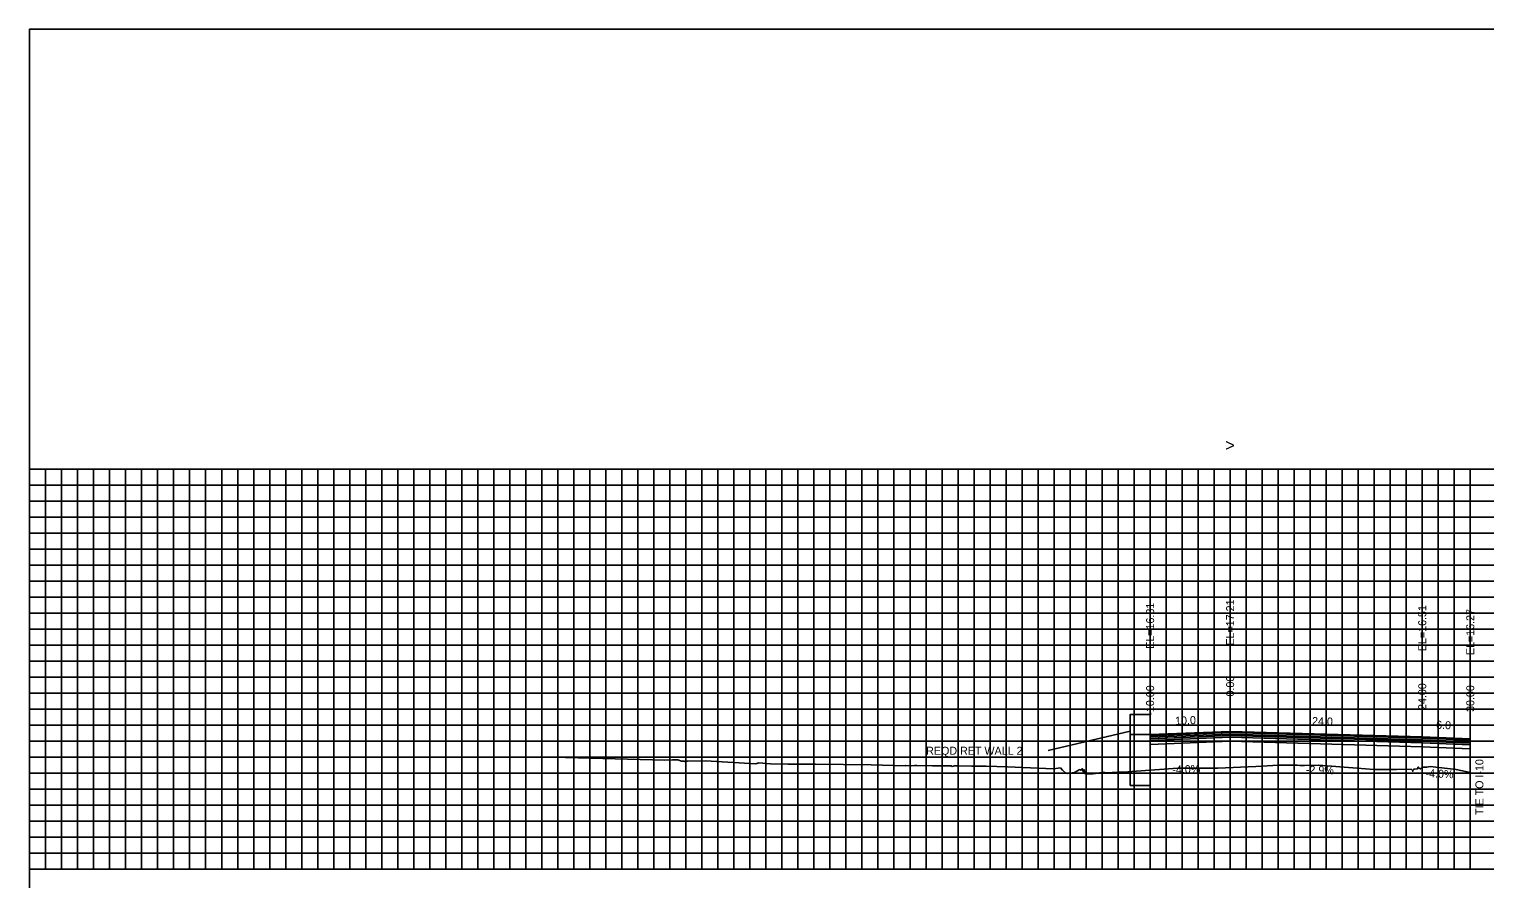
# Model space of a CAD drawing. Extents: x 1797518 to 1804843, y 248068 to 251132.
# Drawn here: x 1803840.9 to 1804022.8, y 250163.2 to 250269.4 of the extents above; entities that cross this region are included whole.
import ezdxf

# ---------------------------------------------------------------- set-up
doc = ezdxf.new("R2010")
doc.units = 0
for name, color, linetype in [('3', 7, 'Continuous'), ('4', 7, 'Continuous'), ('60', 7, 'Continuous'), ('BASE', 7, 'Continuous'), ('CL-CNST', 7, 'Continuous'), ('Level 62', 7, 'Continuous'), ('LOWER BINDER', 7, 'Continuous'), ('M-ROADS', 7, 'Continuous'), ('UPPER BINDER', 7, 'Continuous'), ('WEARING', 7, 'Continuous')]:
    doc.layers.add(name, color=color, linetype=linetype)

msp = doc.modelspace()

# ---------------------------------------------------------------- linework, layer by layer
for p, q in [((1803981, 250181.25), (1803981, 250183.25)), ((1803991, 250181.65), (1803991, 250183.65)), ((1804015, 250180.95), (1804015, 250182.95)), ((1804021, 250180.71), (1804021, 250182.71))]:
    msp.add_line(p, q)
msp.add_lwpolyline([(1803841, 250079.43), (1804141, 250079.43), (1804141, 250269.43), (1803841, 250269.43)], close=True)
at = {"layer": '3'}
for p, q in [((1803968.28, 250179.28), (1803978.5, 250181.68)), ((1804021, 250181.46), (1804021, 250171.43))]:
    msp.add_line(p, q, dxfattribs=at)
at = {"layer": '60'}
for p, q in [((1803840.94, 250214.43), (1803841, 250214.43)), ((1803841, 250164.43), (1803841, 250214.43)), ((1803840.94, 250204.43), (1803841, 250204.43)), ((1803840.94, 250194.43), (1803841, 250194.43)), ((1803840.94, 250184.43), (1803841, 250184.43)), ((1803840.94, 250174.43), (1803841, 250174.43)), ((1803840.94, 250164.43), (1803841, 250164.43)), ((1803841, 250164.43), (1804141, 250164.43)), ((1803841, 250164.37), (1803841, 250164.43)), ((1803851, 250164.37), (1803851, 250164.43)), ((1803861, 250164.37), (1803861, 250164.43)), ((1803871, 250164.37), (1803871, 250164.43)), ((1803881, 250164.37), (1803881, 250164.43)), ((1803891, 250164.37), (1803891, 250164.43)), ((1803901, 250164.37), (1803901, 250164.43)), ((1803911, 250164.37), (1803911, 250164.43)), ((1803921, 250164.37), (1803921, 250164.43)), ((1803931, 250164.37), (1803931, 250164.43)), ((1803941, 250164.37), (1803941, 250164.43)), ((1803951, 250164.37), (1803951, 250164.43)), ((1803961, 250164.37), (1803961, 250164.43)), ((1803971, 250164.37), (1803971, 250164.43)), ((1803981, 250164.37), (1803981, 250164.43)), ((1803991, 250164.37), (1803991, 250164.43)), ((1804001, 250164.37), (1804001, 250164.43)), ((1804011, 250164.37), (1804011, 250164.43)), ((1804021, 250164.37), (1804021, 250164.43))]:
    msp.add_line(p, q, dxfattribs=at)
at = {"layer": 'BASE'}
msp.add_lwpolyline([(1803981, 250180.53), (1803991, 250180.93), (1804015, 250180.23), (1804021, 250179.98), (1804021, 250179.48), (1804015, 250179.73), (1803991, 250180.43), (1803981, 250180.03)], close=True, dxfattribs=at)
at = {"layer": 'CL-CNST'}
for points in [[(1803981, 250181.25), (1803978.5, 250181.25), (1803978.5, 250183.75), (1803981, 250183.75)], [(1803978.5, 250174.87), (1803981, 250174.87), (1803981, 250181.25), (1803978.5, 250181.25)]]:
    msp.add_lwpolyline(points, close=True, dxfattribs=at)
msp.add_lwpolyline([(1803981, 250181.25), (1803991, 250181.65), (1804015, 250180.95), (1804021, 250180.71)], dxfattribs=at)
at = {"layer": 'Level 62'}
for p, q in [((1803841, 250214.43), (1804141, 250214.43)), ((1803841, 250164.43), (1803841, 250214.43)), ((1803843, 250164.43), (1803843, 250214.43)), ((1803845, 250164.43), (1803845, 250214.43)), ((1803847, 250164.43), (1803847, 250214.43)), ((1803849, 250164.43), (1803849, 250214.43)), ((1803851, 250164.43), (1803851, 250214.43)), ((1803853, 250164.43), (1803853, 250214.43)), ((1803855, 250164.43), (1803855, 250214.43)), ((1803857, 250164.43), (1803857, 250214.43)), ((1803859, 250164.43), (1803859, 250214.43)), ((1803861, 250164.43), (1803861, 250214.43)), ((1803863, 250164.43), (1803863, 250214.43)), ((1803865, 250164.43), (1803865, 250214.43)), ((1803867, 250164.43), (1803867, 250214.43)), ((1803869, 250164.43), (1803869, 250214.43)), ((1803871, 250164.43), (1803871, 250214.43)), ((1803873, 250164.43), (1803873, 250214.43)), ((1803875, 250164.43), (1803875, 250214.43)), ((1803877, 250164.43), (1803877, 250214.43)), ((1803879, 250164.43), (1803879, 250214.43)), ((1803881, 250164.43), (1803881, 250214.43)), ((1803883, 250164.43), (1803883, 250214.43)), ((1803885, 250164.43), (1803885, 250214.43)), ((1803887, 250164.43), (1803887, 250214.43)), ((1803889, 250164.43), (1803889, 250214.43)), ((1803891, 250164.43), (1803891, 250214.43)), ((1803893, 250164.43), (1803893, 250214.43)), ((1803895, 250164.43), (1803895, 250214.43)), ((1803897, 250164.43), (1803897, 250214.43)), ((1803899, 250164.43), (1803899, 250214.43)), ((1803901, 250164.43), (1803901, 250214.43)), ((1803903, 250164.43), (1803903, 250214.43)), ((1803905, 250164.43), (1803905, 250214.43)), ((1803907, 250164.43), (1803907, 250214.43)), ((1803909, 250164.43), (1803909, 250214.43)), ((1803911, 250164.43), (1803911, 250214.43)), ((1803913, 250164.43), (1803913, 250214.43)), ((1803915, 250164.43), (1803915, 250214.43)), ((1803917, 250164.43), (1803917, 250214.43)), ((1803919, 250164.43), (1803919, 250214.43)), ((1803921, 250164.43), (1803921, 250214.43)), ((1803923, 250164.43), (1803923, 250214.43)), ((1803925, 250164.43), (1803925, 250214.43)), ((1803927, 250164.43), (1803927, 250214.43)), ((1803929, 250164.43), (1803929, 250214.43)), ((1803931, 250164.43), (1803931, 250214.43)), ((1803933, 250164.43), (1803933, 250214.43)), ((1803935, 250164.43), (1803935, 250214.43)), ((1803937, 250164.43), (1803937, 250214.43)), ((1803939, 250164.43), (1803939, 250214.43)), ((1803941, 250164.43), (1803941, 250214.43)), ((1803943, 250164.43), (1803943, 250214.43)), ((1803945, 250164.43), (1803945, 250214.43)), ((1803947, 250164.43), (1803947, 250214.43)), ((1803949, 250164.43), (1803949, 250214.43)), ((1803951, 250164.43), (1803951, 250214.43)), ((1803953, 250164.43), (1803953, 250214.43)), ((1803955, 250164.43), (1803955, 250214.43)), ((1803957, 250164.43), (1803957, 250214.43)), ((1803959, 250164.43), (1803959, 250214.43)), ((1803961, 250164.43), (1803961, 250214.43)), ((1803963, 250164.43), (1803963, 250214.43)), ((1803965, 250164.43), (1803965, 250214.43)), ((1803967, 250164.43), (1803967, 250214.43)), ((1803969, 250164.43), (1803969, 250214.43)), ((1803971, 250164.43), (1803971, 250214.43)), ((1803973, 250164.43), (1803973, 250214.43)), ((1803975, 250164.43), (1803975, 250214.43)), ((1803977, 250164.43), (1803977, 250214.43)), ((1803979, 250164.43), (1803979, 250214.43)), ((1803981, 250164.43), (1803981, 250214.43)), ((1803983, 250164.43), (1803983, 250214.43)), ((1803985, 250164.43), (1803985, 250214.43)), ((1803987, 250164.43), (1803987, 250214.43)), ((1803989, 250164.43), (1803989, 250214.43)), ((1803991, 250164.43), (1803991, 250214.43)), ((1803993, 250164.43), (1803993, 250214.43)), ((1803995, 250164.43), (1803995, 250214.43)), ((1803997, 250164.43), (1803997, 250214.43)), ((1803999, 250164.43), (1803999, 250214.43)), ((1804001, 250164.43), (1804001, 250214.43)), ((1804003, 250164.43), (1804003, 250214.43)), ((1804005, 250164.43), (1804005, 250214.43)), ((1804007, 250164.43), (1804007, 250214.43)), ((1804009, 250164.43), (1804009, 250214.43)), ((1804011, 250164.43), (1804011, 250214.43)), ((1804013, 250164.43), (1804013, 250214.43)), ((1804015, 250164.43), (1804015, 250214.43)), ((1804017, 250164.43), (1804017, 250214.43)), ((1804019, 250164.43), (1804019, 250214.43)), ((1804021, 250164.43), (1804021, 250214.43)), ((1803841, 250212.43), (1804141, 250212.43)), ((1803841, 250210.43), (1804141, 250210.43)), ((1803841, 250208.43), (1804141, 250208.43)), ((1803841, 250206.43), (1804141, 250206.43)), ((1803841, 250204.43), (1804141, 250204.43)), ((1803841, 250202.43), (1804141, 250202.43)), ((1803841, 250200.43), (1804141, 250200.43)), ((1803841, 250198.43), (1804141, 250198.43)), ((1803841, 250196.43), (1804141, 250196.43)), ((1803841, 250194.43), (1804141, 250194.43)), ((1803841, 250192.43), (1804141, 250192.43)), ((1803841, 250190.43), (1804141, 250190.43)), ((1803841, 250188.43), (1804141, 250188.43)), ((1803841, 250186.43), (1804141, 250186.43)), ((1803841, 250184.43), (1804141, 250184.43)), ((1803841, 250182.43), (1804141, 250182.43)), ((1803841, 250180.43), (1804141, 250180.43)), ((1803841, 250178.43), (1804141, 250178.43)), ((1803841, 250176.43), (1804141, 250176.43)), ((1803841, 250174.43), (1804141, 250174.43)), ((1803841, 250172.43), (1804141, 250172.43)), ((1803841, 250170.43), (1804141, 250170.43)), ((1803841, 250168.43), (1804141, 250168.43)), ((1803841, 250166.43), (1804141, 250166.43)), ((1803841, 250164.43), (1804141, 250164.43))]:
    msp.add_line(p, q, dxfattribs=at)
at = {"layer": 'LOWER BINDER'}
for points in [[(1803991, 250181.31), (1804015, 250180.61), (1804021, 250180.36), (1804021, 250180.17), (1804015, 250180.42), (1803991, 250181.12), (1803981, 250180.72), (1803981, 250180.91)], [(1803991, 250181.12), (1804015, 250180.42), (1804021, 250180.17), (1804021, 250179.98), (1804015, 250180.23), (1803991, 250180.93), (1803981, 250180.53), (1803981, 250180.72)]]:
    msp.add_lwpolyline(points, close=True, dxfattribs=at)
at = {"layer": 'M-ROADS'}
msp.add_lwpolyline([(1803904.86, 250178.46), (1803920.37, 250178.05), (1803921.31, 250178.08), (1803921.98, 250178.08), (1803922.44, 250177.93), (1803922.8, 250177.93), (1803922.8, 250177.87), (1803922.99, 250177.93), (1803923.19, 250177.93), (1803925.47, 250177.95), (1803931.75, 250177.6), (1803932.11, 250177.72), (1803933.55, 250177.6), (1803935.75, 250177.55), (1803939.21, 250177.56), (1803946.15, 250177.47), (1803950.41, 250177.35), (1803950.43, 250177.4), (1803950.44, 250177.4), (1803951.18, 250177.35), (1803951.56, 250177.38), (1803951.8, 250177.4), (1803951.84, 250177.37), (1803953.8, 250177.36), (1803954.33, 250177.36), (1803954.38, 250177.36), (1803954.42, 250177.36), (1803955.67, 250177.34), (1803956.15, 250177.34), (1803956.25, 250177.27), (1803956.54, 250177.33), (1803956.99, 250177.36), (1803956.99, 250177.36), (1803958.71, 250177.31), (1803960.51, 250177.31), (1803963.19, 250177.2), (1803968.94, 250176.97), (1803969.79, 250177.08), (1803970.07, 250176.8), (1803970.47, 250176.42), (1803970.7, 250176.37), (1803971.57, 250176.52), (1803972.2, 250176.87), (1803972.35, 250176.78), (1803972.35, 250176.85), (1803972.36, 250176.78), (1803972.37, 250176.87), (1803972.49, 250176.99), (1803972.68, 250176.57), (1803972.73, 250176.83), (1803972.74, 250176.87), (1803972.74, 250176.87), (1803972.83, 250176.39), (1803972.84, 250176.4), (1803972.84, 250176.4), (1803972.84, 250176.39), (1803972.85, 250176.39), (1803972.98, 250176.33), (1803973, 250176.33), (1803973.1, 250176.31), (1803973.85, 250176.34), (1803974.18, 250176.39), (1803975.19, 250176.54), (1803975.19, 250176.54), (1803975.5, 250176.47), (1803976.99, 250176.55), (1803977.67, 250176.55), (1803978.71, 250176.62), (1803984.47, 250177.06), (1803985.56, 250177.05), (1803986.77, 250177.05), (1803987.04, 250177.04), (1803987.19, 250177.04), (1803987.9, 250177.04), (1803989.44, 250177.06), (1803994.22, 250177.28), (1803997.05, 250177.41), (1803997.99, 250177.42), (1803999.37, 250177.42), (1803999.69, 250177.4), (1803999.8, 250177.4), (1804000.29, 250177.4), (1804002.02, 250177.41), (1804006.85, 250177.04), (1804008.96, 250176.88), (1804009.73, 250176.89), (1804011.29, 250176.89), (1804011.65, 250176.89), (1804011.72, 250176.89), (1804011.75, 250176.89), (1804011.79, 250176.89), (1804013.6, 250176.94), (1804013.81, 250176.72), (1804013.81, 250176.65), (1804013.82, 250176.72), (1804013.83, 250176.74), (1804013.84, 250176.75), (1804013.85, 250176.79), (1804013.87, 250176.83), (1804013.9, 250176.86), (1804013.92, 250176.88), (1804013.99, 250176.91), (1804014.41, 250176.97), (1804014.5, 250177.18), (1804014.54, 250177.1), (1804014.8, 250176.95), (1804014.98, 250177.16), (1804015.22, 250177.16), (1804015.56, 250177.17), (1804016.01, 250177.24), (1804019.22, 250176.89), (1804021, 250176.49)], dxfattribs=at)
at = {"layer": 'UPPER BINDER'}
msp.add_lwpolyline([(1804021, 250180.36), (1804021, 250180.55), (1804015, 250180.8), (1803991, 250181.5), (1803981, 250181.1), (1803981, 250180.91), (1803991, 250181.31), (1804015, 250180.61)], close=True, dxfattribs=at)
at = {"layer": 'WEARING'}
msp.add_lwpolyline([(1804021, 250180.55), (1804021, 250180.71), (1804015, 250180.95), (1803991, 250181.65), (1803981, 250181.25), (1803981, 250181.1), (1803991, 250181.5), (1804015, 250180.8)], close=True, dxfattribs=at)

# ---------------------------------------------------------------- texts
at = {"layer": '3'}
for s, p in [('EL=16.81', (1803981.5, 250191.97)), ('EL=17.21', (1803991.5, 250192.37)), ('EL=16.51', (1804015.5, 250191.67)), ('EL=16.27', (1804021.5, 250191.18)), ('0.00', (1803991.5, 250186.01)), ('24.00', (1804015.5, 250184.32)), ('-10.00', (1803981.5, 250183.62)), ('30.00', (1804021.5, 250184.08)), ('TIE TO I-10', (1804022.64, 250171.2))]:
    msp.add_text(s, height=1, rotation=90, dxfattribs=at).set_placement(p)
msp.add_text('REQD RET WALL 2', height=1, dxfattribs=at).set_placement((1803953.02, 250178.73))
at = {"layer": '4'}
for s, rotation, p in [('10.0', 2.2906, (1803984.14, 250182.47)), ('24.0', 358.3274, (1804001.22, 250182.45)), ('6.0', 357.7094, (1804016.72, 250181.98)), ('-4.0%', 2.2906, (1803983.79, 250176.35)), ('-2.9%', 358.3274, (1804000.45, 250176.37)), ('-4.0%', 357.7094, (1804015.39, 250175.93))]:
    msp.add_text(s, height=1, rotation=rotation, dxfattribs=at).set_placement(p)
at = {"layer": '60'}
for s, height, p in [('>', 1.5, (1803990.39, 250216.68)), ('-', 0.0001, (1803841, 250164.43))]:
    msp.add_text(s, height=height, dxfattribs=at).set_placement(p)

doc.saveas('drawing.dxf')
